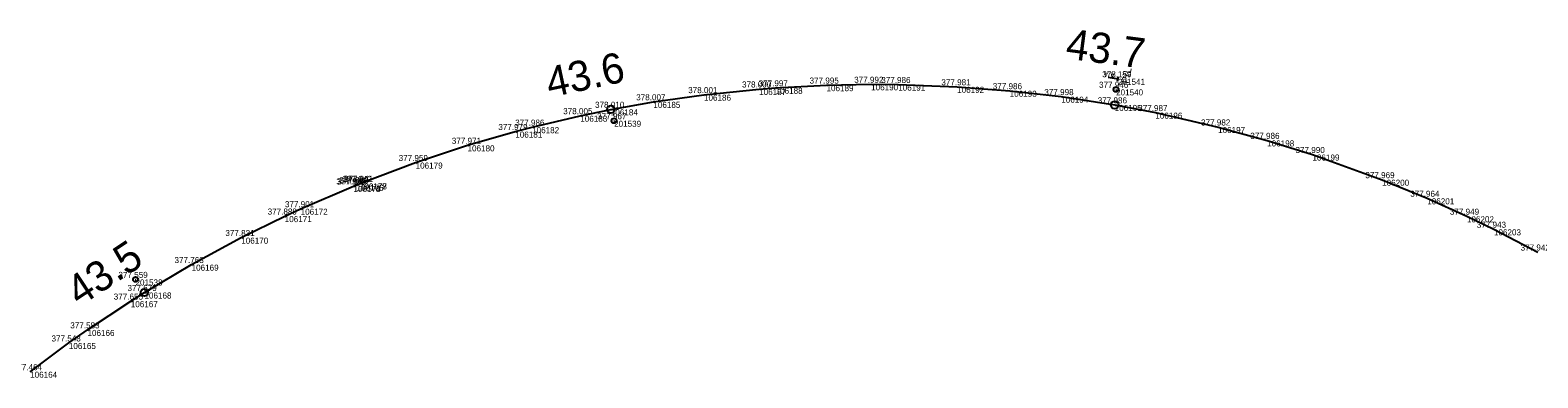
# Model space of a CAD drawing. Extents: x -545715 to -485912, y -1154994 to -1140055.
# Drawn here: x -512503.4 to -512204.7, y -1143315.7 to -1143246.8 of the extents above; entities that cross this region are included whole.
import ezdxf

# ---------------------------------------------------------------- set-up
doc = ezdxf.new("R2010")
doc.units = 0
for name, color, linetype in [('Vrstva 1', 7, 'Continuous'), ('Vrstva 6', 7, 'Continuous'), ('Vrstva 60', 7, 'Continuous'), ('Vrstva 61', 7, 'Continuous'), ('Vrstva 7', 7, 'Continuous')]:
    doc.layers.add(name, color=color, linetype=linetype)

msp = doc.modelspace()

# ---------------------------------------------------------------- linework, layer by layer
at = {"layer": 'Vrstva 1'}
for p, q in [((-512345.61, -1143257.71), (-512336.77, -1143257.55)), ((-512336.77, -1143257.55), (-512331.4, -1143257.6)), ((-512331.4, -1143257.6), (-512319.72, -1143258.04)), ((-512379.92, -1143261.02), (-512369.89, -1143259.61)), ((-512369.89, -1143259.61), (-512358.96, -1143258.48)), ((-512358.96, -1143258.48), (-512355.7, -1143258.24)), ((-512355.7, -1143258.24), (-512345.61, -1143257.71)), ((-512319.72, -1143258.04), (-512309.31, -1143258.82)), ((-512309.31, -1143258.82), (-512299.09, -1143259.99)), ((-512299.09, -1143259.99), (-512288.51, -1143261.63)), ((-512394.4, -1143263.77), (-512388.34, -1143262.51)), ((-512388.34, -1143262.51), (-512379.92, -1143261.02)), ((-512288.51, -1143261.63), (-512280.45, -1143263.16)), ((-512280.45, -1143263.16), (-512268.01, -1143266.01)), ((-512407.28, -1143266.91), (-512403.94, -1143266.04)), ((-512403.94, -1143266.04), (-512394.4, -1143263.77)), ((-512268.01, -1143266.01), (-512258.29, -1143268.66)), ((-512427.03, -1143273.04), (-512416.74, -1143269.64)), ((-512416.74, -1143269.64), (-512407.28, -1143266.91)), ((-512258.29, -1143268.66), (-512249.32, -1143271.46)), ((-512249.32, -1143271.46), (-512235.51, -1143276.45)), ((-512438.1, -1143277.19), (-512427.03, -1143273.04)), ((-512449.81, -1143282.2), (-512439.35, -1143277.7)), ((-512439.35, -1143277.7), (-512438.1, -1143277.19)), ((-512235.51, -1143276.45), (-512226.57, -1143280.13)), ((-512226.57, -1143280.13), (-512218.71, -1143283.69)), ((-512461.58, -1143287.92), (-512452.97, -1143283.66)), ((-512452.97, -1143283.66), (-512449.81, -1143282.2)), ((-512218.71, -1143283.69), (-512213.35, -1143286.28)), ((-512213.35, -1143286.28), (-512204.66, -1143290.79)), ((-512471.42, -1143293.27), (-512461.58, -1143287.92)), ((-512480.76, -1143298.8), (-512471.42, -1143293.27)), ((-512483.47, -1143300.51), (-512480.76, -1143298.8)), ((-512492.05, -1143306.21), (-512483.47, -1143300.51)), ((-512495.74, -1143308.8), (-512492.05, -1143306.21)), ((-512503.41, -1143314.49), (-512495.74, -1143308.8))]:
    msp.add_line(p, q, dxfattribs=at)
at = {"layer": 'Vrstva 6'}
for p, q in [((-512289.79, -1143256.12), (-512287.85, -1143256.46)), ((-512287.93, -1143256.95), (-512287.76, -1143255.97))]:
    msp.add_line(p, q, dxfattribs=at)
at = {"layer": 'Vrstva 60'}
for p, q in [((-512336.77, -1143257.55), (-512336.77, -1143257.55)), ((-512331.4, -1143257.6), (-512331.4, -1143257.6)), ((-512287.85, -1143256.46), (-512287.85, -1143256.46)), ((-512369.89, -1143259.61), (-512369.89, -1143259.61)), ((-512358.96, -1143258.48), (-512358.96, -1143258.48)), ((-512355.7, -1143258.24), (-512355.7, -1143258.24)), ((-512345.61, -1143257.71), (-512345.61, -1143257.71)), ((-512319.72, -1143258.04), (-512319.72, -1143258.04)), ((-512309.31, -1143258.82), (-512309.31, -1143258.82)), ((-512299.09, -1143259.99), (-512299.09, -1143259.99)), ((-512288.23, -1143258.55), (-512288.23, -1143258.55)), ((-512388.34, -1143262.51), (-512388.34, -1143262.51)), ((-512379.92, -1143261.02), (-512379.92, -1143261.02)), ((-512288.51, -1143261.63), (-512288.51, -1143261.63)), ((-512280.45, -1143263.16), (-512280.45, -1143263.16)), ((-512403.94, -1143266.04), (-512403.94, -1143266.04)), ((-512394.4, -1143263.77), (-512394.4, -1143263.77)), ((-512387.7, -1143264.77), (-512387.7, -1143264.77)), ((-512268.01, -1143266.01), (-512268.01, -1143266.01)), ((-512416.74, -1143269.64), (-512416.74, -1143269.64)), ((-512407.28, -1143266.91), (-512407.28, -1143266.91)), ((-512258.29, -1143268.66), (-512258.29, -1143268.66)), ((-512249.32, -1143271.46), (-512249.32, -1143271.46)), ((-512427.03, -1143273.04), (-512427.03, -1143273.04)), ((-512439.35, -1143277.69), (-512439.35, -1143277.69)), ((-512439.35, -1143277.7), (-512439.35, -1143277.7)), ((-512438.74, -1143277.45), (-512438.74, -1143277.45)), ((-512438.73, -1143277.45), (-512438.73, -1143277.45)), ((-512438.1, -1143277.19), (-512438.1, -1143277.19)), ((-512438.08, -1143277.18), (-512438.08, -1143277.18)), ((-512235.51, -1143276.45), (-512235.51, -1143276.45)), ((-512226.57, -1143280.13), (-512226.57, -1143280.13)), ((-512452.97, -1143283.66), (-512452.97, -1143283.66)), ((-512449.81, -1143282.2), (-512449.81, -1143282.2)), ((-512218.71, -1143283.69), (-512218.71, -1143283.69)), ((-512213.35, -1143286.28), (-512213.35, -1143286.28)), ((-512461.58, -1143287.92), (-512461.58, -1143287.92)), ((-512471.42, -1143293.27), (-512471.42, -1143293.27)), ((-512204.66, -1143290.79), (-512204.66, -1143290.79)), ((-512482.53, -1143296.21), (-512482.53, -1143296.21)), ((-512480.76, -1143298.8), (-512480.76, -1143298.8)), ((-512483.47, -1143300.51), (-512483.47, -1143300.51)), ((-512492.05, -1143306.21), (-512492.05, -1143306.21)), ((-512495.74, -1143308.8), (-512495.74, -1143308.8))]:
    msp.add_line(p, q, dxfattribs=at)
at = {"layer": 'Vrstva 7'}
for p, q in [((-512288.28, -1143258.55), (-512288.18, -1143258.55)), ((-512387.75, -1143264.77), (-512387.65, -1143264.77)), ((-512482.58, -1143296.21), (-512482.48, -1143296.21))]:
    msp.add_line(p, q, dxfattribs=at)
for centre, radius in [((-512288.23, -1143258.55), 0.5), ((-512388.34, -1143262.51), 0.75), ((-512288.51, -1143261.63), 0.75), ((-512387.7, -1143264.77), 0.5), ((-512482.53, -1143296.21), 0.5), ((-512480.76, -1143298.8), 0.75)]:
    msp.add_circle(centre, radius, dxfattribs=at)

# ---------------------------------------------------------------- texts
at = {"layer": 'Vrstva 6'}
for s, height, rotation, p in [('PřL', 1.5, 78.4684, (-512285.75, -1143257.48)), ('  A A ', 1, 170, (-512287.67, -1143255.48))]:
    msp.add_text(s, height=height, rotation=rotation, dxfattribs=at).set_placement(p)
at = {"layer": 'Vrstva 60'}
for s, p in [('106189', (-512345.61, -1143258.91)), ('106190', (-512336.77, -1143258.75)), ('106191', (-512331.4, -1143258.8)), ('201541', (-512287.85, -1143257.66)), ('106186', (-512369.89, -1143260.8)), ('106187', (-512358.96, -1143259.68)), ('106188', (-512355.7, -1143259.44)), ('106192', (-512319.72, -1143259.24)), ('106193', (-512309.31, -1143260.02)), ('106194', (-512299.09, -1143261.19)), ('201540', (-512288.23, -1143259.75)), ('106184', (-512388.34, -1143263.71)), ('106185', (-512379.92, -1143262.22)), ('106195', (-512288.51, -1143262.83)), ('106196', (-512280.45, -1143264.36)), ('106182', (-512403.94, -1143267.24)), ('106183', (-512394.4, -1143264.97)), ('201539', (-512387.7, -1143265.97)), ('106197', (-512268.01, -1143267.21)), ('106180', (-512416.74, -1143270.84)), ('106181', (-512407.28, -1143268.11)), ('106198', (-512258.29, -1143269.86)), ('106199', (-512249.32, -1143272.66)), ('106179', (-512427.03, -1143274.25)), ('106173', (-512439.35, -1143278.89)), ('106174', (-512439.35, -1143278.9)), ('106175', (-512438.74, -1143278.65)), ('106176', (-512438.73, -1143278.65)), ('106177', (-512438.1, -1143278.39)), ('106178', (-512438.08, -1143278.38)), ('106200', (-512235.51, -1143277.65)), ('106201', (-512226.57, -1143281.33)), ('106171', (-512452.97, -1143284.86)), ('106172', (-512449.81, -1143283.4)), ('106202', (-512218.71, -1143284.89)), ('106203', (-512213.35, -1143287.48)), ('106170', (-512461.58, -1143289.12)), ('106169', (-512471.42, -1143294.47)), ('201538', (-512482.53, -1143297.41)), ('106168', (-512480.76, -1143300)), ('106167', (-512483.47, -1143301.71)), ('106166', (-512492.05, -1143307.41)), ('106165', (-512495.74, -1143310)), ('106164', (-512503.41, -1143315.69))]:
    msp.add_text(s, height=1.2, dxfattribs=at).set_placement(p)
at = {"layer": 'Vrstva 61'}
for s, p in [('378.000', (-512362.35, -1143258.18)), ('377.997', (-512359.06, -1143257.94)), ('377.995', (-512348.97, -1143257.41)), ('377.992', (-512340.13, -1143257.25)), ('377.986', (-512334.76, -1143257.3)), ('377.981', (-512322.85, -1143257.74)), ('377.986', (-512312.67, -1143258.52)), ('377.946', (-512291.61, -1143258.25)), ('378.159', (-512290.97, -1143256.16)), ('378.007', (-512383.32, -1143260.72)), ('378.001', (-512373.02, -1143259.3)), ('377.998', (-512302.45, -1143259.69)), ('377.986', (-512291.87, -1143261.33)), ('378.005', (-512397.79, -1143263.47)), ('378.010', (-512391.48, -1143262.21)), ('377.967', (-512391.06, -1143264.47)), ('377.987', (-512283.84, -1143262.86)), ('377.979', (-512410.64, -1143266.61)), ('377.986', (-512407.3, -1143265.74)), ('377.982', (-512271.39, -1143265.71)), ('377.971', (-512419.86, -1143269.34)), ('377.986', (-512261.64, -1143268.36)), ('377.959', (-512430.39, -1143272.75)), ('377.990', (-512252.67, -1143271.16)), ('377.969', (-512238.84, -1143276.15)), ('377.938', (-512442.74, -1143277.4)), ('377.941', (-512442.51, -1143277.39)), ('377.940', (-512442.15, -1143277.15)), ('377.943', (-512442.14, -1143277.15)), ('377.942', (-512441.51, -1143276.89)), ('377.941', (-512441.24, -1143276.88)), ('377.964', (-512229.95, -1143279.83)), ('377.901', (-512452.93, -1143281.9)), ('377.889', (-512456.35, -1143283.36)), ('377.949', (-512222.09, -1143283.39)), ('377.831', (-512464.73, -1143287.62)), ('377.943', (-512216.76, -1143285.98)), ('377.942', (-512208.07, -1143290.49)), ('377.763', (-512474.81, -1143292.97)), ('377.559', (-512485.92, -1143295.91)), ('377.655', (-512486.85, -1143300.21)), ('377.679', (-512484.12, -1143298.5)), ('377.583', (-512495.46, -1143305.91)), ('377.548', (-512499.18, -1143308.5)), ('377.464', (-512506.85, -1143314.19))]:
    msp.add_text(s, height=1.2, dxfattribs=at).set_placement(p)
at = {"layer": 'Vrstva 7'}
for s, rotation, p in [('43.7', 352.5299, (-512298.39, -1143252.42)), ('43.6', 12.114, (-512400.48, -1143260.21)), ('43.5', 33.4053, (-512493.64, -1143301.7))]:
    msp.add_text(s, height=6, rotation=rotation, dxfattribs=at).set_placement(p)

doc.saveas('drawing.dxf')
